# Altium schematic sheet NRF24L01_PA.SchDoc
size A4
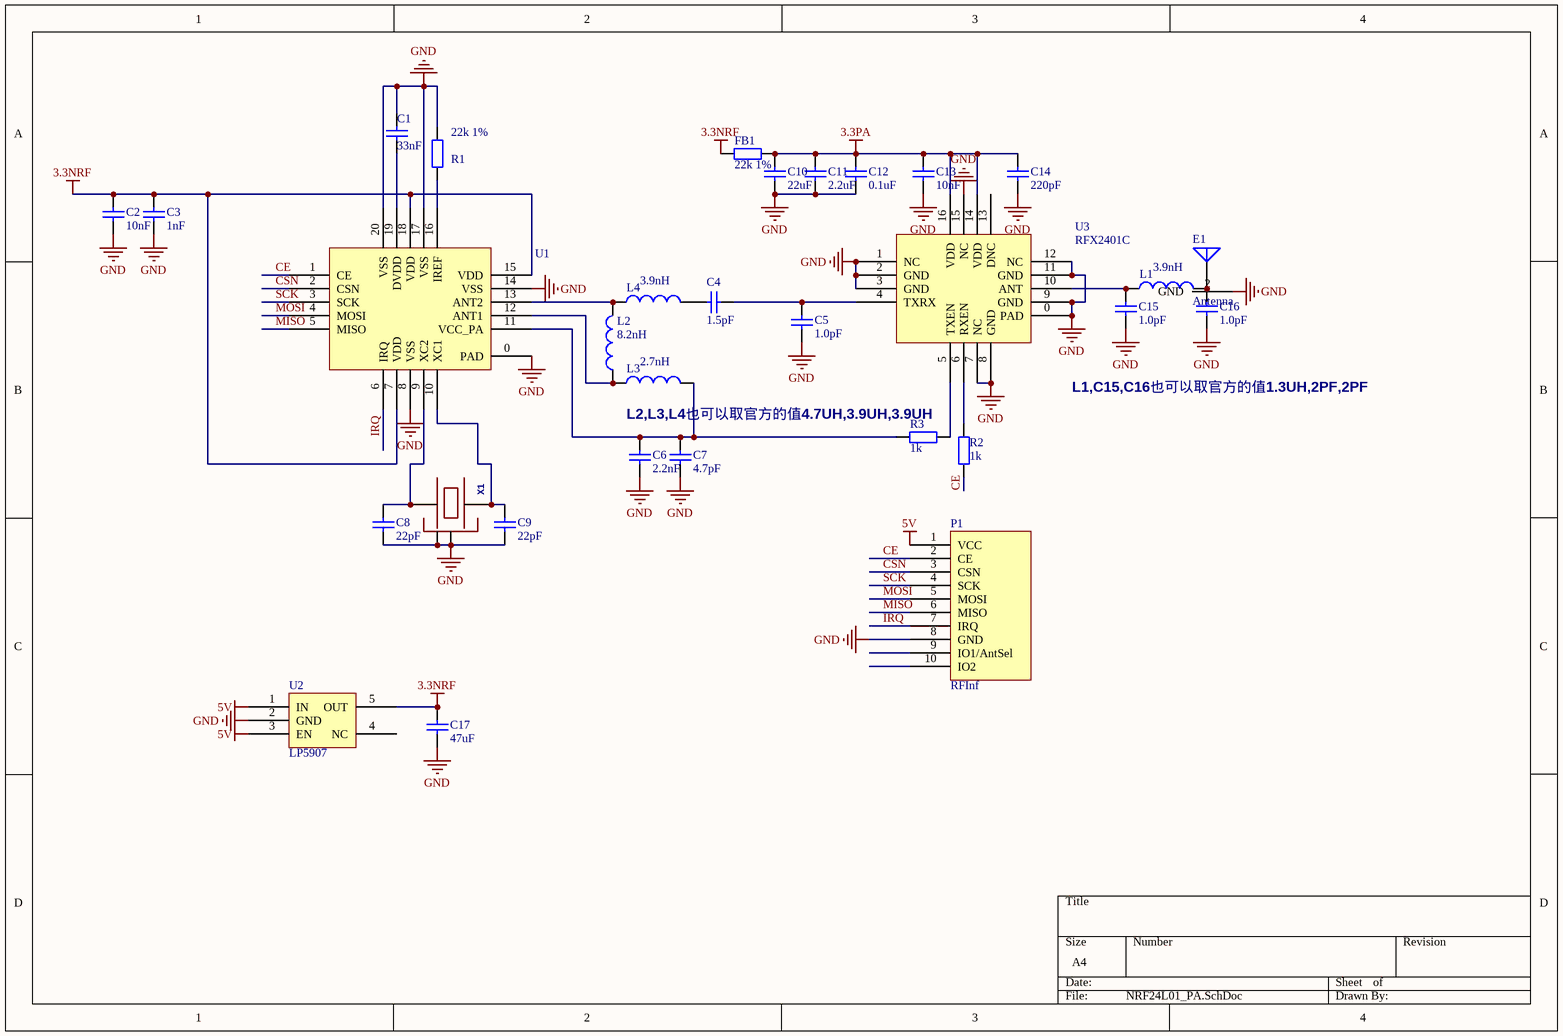
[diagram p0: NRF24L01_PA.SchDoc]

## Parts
C1  value 33nF  [0402]  (hidden comment: Cap)
C2  value 10nF  [0402]  (hidden comment: Cap)
C3  value 1nF  [0402]  (hidden comment: Cap)
C4  value 1.5pF  [0402]  (hidden comment: Cap)
C5  value 1.0pF  [0402]  (hidden comment: Cap)
C6  value 2.2nF  [0402]  (hidden comment: Cap)
C7  value 4.7pF  [0402]  (hidden comment: Cap)
C8  value 22pF  [0402]  (hidden comment: Cap)
C9  value 22pF  [0402]  (hidden comment: Cap)
C10  value 22uF  [0805]  (hidden comment: Cap)
C11  value 2.2uF  [0402]  (hidden comment: Cap)
C12  value 0.1uF  [0402]  (hidden comment: Cap)
C13  value 10nF  [0402]  (hidden comment: Cap)
C14  value 220pF  [0402]  (hidden comment: Cap)
C15  value 1.0pF  [0402]  (hidden comment: Cap)
C16  value 1.0pF  [0402]  (hidden comment: Cap)
C17  value 47uF  [0805]  (hidden comment: Cap)
E1  Antenna  [IPEX]
FB1  value 22k 1%  [0603]  (hidden comment: Res2)
L1  value 3.9nH  [0402]  (hidden comment: Inductor)
L2  value 8.2nH  [0402]  (hidden comment: Inductor)
L3  value 2.7nH  [0402]  (hidden comment: Inductor)
L4  value 3.9nH  [0402]  (hidden comment: Inductor)
P1  RFInf  [RFInf]
R1  value 22k 1%  [0402]  (hidden comment: Res2)
R2  value 1k  [0402]  (hidden comment: Res2)
R3  value 1k  [0402]  (hidden comment: Res2)
U1  NRF24L01  [NRF24L01]  (value not drawn)
U2  LP5907  [SOT23-5]
U3  RFX2401C  [RFX2401C]
X1  16Mhz  [OSCILLATOR-3.2X2.5]  (value not drawn)

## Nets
3.3NRF: C2.1 C3.1 C17.1 FB1.1 U1.7(VDD) U1.15(VDD) U1.18(VDD) U2.5(OUT)
3.3PA: C10.1 C11.1 C12.1 C13.1 C14.1 FB1.2 U3.14(VDD) U3.16(VDD)
5V: P1.1(VCC) U2.1(IN) U2.3(EN)
GND: C1.1 C2.2 C3.2 C5.2 C6.2 C7.2 C8.2 C9.2 C10.2 C11.2 C12.2 C13.2 C14.2 C15.2 C16.2 C17.2 E1.2(GND) P1.8(GND) R1.1 U1.0(PAD) U1.8(VSS) U1.14(VSS) U1.17(VSS) U1.20(VSS) U2.2(GND) U3.0(PAD) U3.1(NC) U3.2(GND) U3.3(GND) U3.7(NC) U3.8(GND) U3.9(GND) U3.11(GND) U3.12(NC) U3.15(NC) X1.2(NC_2) X1.4(NC_4)
CE: P1.2(CE) R2.1 U1.1(CE)
CSN: P1.3(CSN) U1.2(CSN)
IRQ: P1.7(IRQ) U1.6(IRQ)
MISO: P1.6(MISO) U1.5(MISO)
MOSI: P1.5(MOSI) U1.4(MOSI)
SCK: P1.4(SCK) U1.3(SCK)
NetC1_2: C1.2 U1.19(DVDD)
NetC4_1: C4.1 L4.2
NetC4_2: C4.2 C5.1 U3.4(TXRX)
NetC6_1: C6.1 C7.1 L3.2 R3.1 U1.11(VCC_PA)
NetC8_1: C8.1 U1.9(XC2) X1.1
NetC9_1: C9.1 U1.10(XC1) X1.3
NetC15_1: C15.1 L1.1 U3.10(ANT)
NetC16_1: C16.1 E1.1(ANT) L1.2
NetL2_1: L2.1 L3.1 U1.12(ANT1)
NetL2_2: L2.2 L4.1 U1.13(ANT2)
NetR1_2: R1.2 U1.16(IREF)
NetR2_2: R2.2 U3.6(RXEN)
NetR3_2: R3.2 U3.5(TXEN)

Not connected (* = marked no-connect by the designer): P1 9(IO1/AntSel) 10(IO2); U2 4(NC); U3 13(DNC)

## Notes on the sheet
- L2,L3,L4也可以取官方的值4.7UH,3.9UH,3.9UH
- L1,C15,C16也可以取官方的值1.3UH,2PF,2PF

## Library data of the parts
C1-C17 = Cap: Capacitor
E1 = Antenna: Generic Antenna
FB1 R1-R3 = Res2: Resistor
L1-L4 = Inductor: Code_IEC: 1005
X1 = OSCILLATOR-3.2X2.5: Crystal Oscillator in 3.2x2.5 SMD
